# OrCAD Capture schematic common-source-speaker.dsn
size A
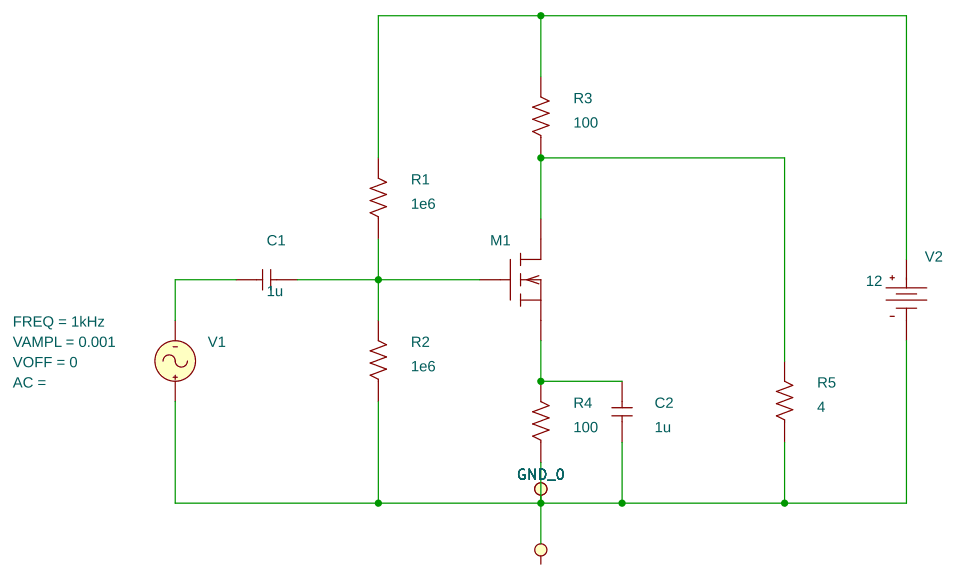
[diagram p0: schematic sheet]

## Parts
C1  1u  [cap196]
C2  1u  [cap196]
M1  MbreakN3
R1  1e6  [AXRC05]
R2  1e6  [AXRC05]
R3  100  [AXRC05]
R4  100  [AXRC05]
R5  4  [AXRC05]
V1  VSIN
V2  VDC

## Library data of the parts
C1 C2 = C
M1 = MbreakN3
R1-R5 = R
V1 = VSIN: FREQ: 1kHz; VAMPL: 0.001; VOFF: 0
V2 = VDC: DC: 12

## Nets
0: C2.1 R2.1 R4.1 R5.1 V1.1(+) V2.1(-)
N15106: M1.2(d) R3.1 R5.2
N15124: C1.2 M1.1(g) R1.1 R2.2
N15156: C1.1 V1.2(-)
N15163: R1.2 R3.2 V2.0(+)
N15735: C2.2 M1.0(s) R4.2
